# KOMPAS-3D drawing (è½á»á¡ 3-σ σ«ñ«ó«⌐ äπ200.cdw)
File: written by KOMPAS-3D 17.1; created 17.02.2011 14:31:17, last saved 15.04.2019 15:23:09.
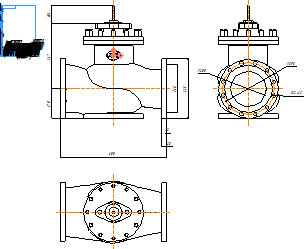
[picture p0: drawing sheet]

Title block, sheet 1: name: Клапан 3-х ходовой Ду200; material: Внимание! Данный продукт является объектом авторского права ООО «Торговый Дом АДЛ». / Запрещается изменение, копирование, распространение / (в том числе путем копирования на другие сайты и ресурсы в Интернете) / или любое иное использование информации и объектов без предварительного / согласия правообладателя (ООО «Торговый Дом АДЛ»).; scale: 1:1; sheets: 1; organisation: ООО "Торговый дом АДЛ"; sheet format: A4; stored path: \\adlc.lan\data\АДЛ_ПКД\3D-модели\ADL production\Клапаны ГРАНРЕГ\Трёхходовой клапан КМ307Ф\KOMPAS 2D\Клапан 3-х ходовой Ду200.cdw

Views: Спереди 1, Проекционный вид 2, Проекционный вид 3
Dimensions and other numbers on the sheet: 600; 3; 28; 268; 335; 170; 295; 22; 200; 367; 101; 1:1; 1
